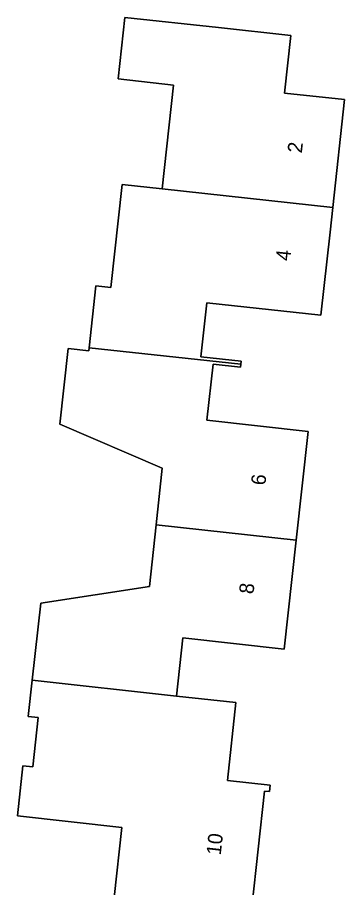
# Model space of a CAD drawing. Extents: x 162184 to 163154, y 385507 to 386516.
# Drawn here: x 162362.2 to 162384.7, y 385954.9 to 386014.8 of the extents above; entities that cross this region are included whole.
import ezdxf

# ---------------------------------------------------------------- set-up
doc = ezdxf.new("R2010")
doc.units = 0
for name, color, linetype in [('IMGEO_Erf', 7, 'Continuous'), ('IMGEO_Pand', 7, 'Continuous'), ('IMGEO_Pand_nummerreeks', 7, 'Continuous')]:
    doc.layers.add(name, color=color, linetype=linetype)

msp = doc.modelspace()

# ---------------------------------------------------------------- linework, layer by layer
at = {"layer": 'IMGEO_Erf'}
msp.add_lwpolyline([(162368.88, 385954.232), (162369.409, 385959.063), (162362.221, 385959.849), (162362.599, 385963.299), (162363.272, 385963.226), (162363.643, 385966.619), (162362.97, 385966.693), (162363.244, 385969.193), (162363.824, 385974.493), (162371.294, 385975.64), (162371.757, 385979.872), (162372.183, 385983.765), (162365.134, 385986.792), (162365.705, 385992.01), (162367.131, 385991.853), (162367.154, 385992.06), (162367.619, 385996.314), (162368.645, 385996.202), (162369.422, 386003.291), (162372.164, 386002.991), (162372.945, 386010.127), (162369.138, 386010.543), (162369.601, 386014.78), (162376.041, 386014.075), (162381.011, 386013.531), (162380.579, 386009.576), (162384.718, 386009.123), (162383.907, 386001.705), (162383.719, 386000), (162383.094, 385994.286), (162375.248, 385995.144), (162374.842, 385991.43), (162377.596, 385991.128), (162377.573, 385990.92), (162377.55, 385990.71), (162375.674, 385990.916), (162375.252, 385987.066), (162382.212, 385986.304), (162381.393, 385978.817), (162380.574, 385971.331), (162373.587, 385972.095), (162373.149, 385968.09), (162377.25, 385967.641), (162376.664, 385962.284), (162379.61, 385961.962), (162379.562, 385961.522), (162379.221, 385961.559), (162378.348, 385953.58)], dxfattribs=at)
at = {"layer": 'IMGEO_Pand'}
for points in [[(162383.907, 386001.705), (162384.718, 386009.123), (162380.579, 386009.576), (162381.011, 386013.531), (162376.041, 386014.075), (162369.601, 386014.78), (162369.138, 386010.543), (162372.945, 386010.127), (162372.164, 386002.991)], [(162367.154, 385992.06), (162377.573, 385990.92), (162377.596, 385991.128), (162374.842, 385991.43), (162375.248, 385995.144), (162383.094, 385994.286), (162383.719, 386000), (162383.907, 386001.705), (162372.164, 386002.991), (162369.422, 386003.291), (162368.645, 385996.202), (162367.619, 385996.314)], [(162371.757, 385979.872), (162381.393, 385978.817), (162382.212, 385986.304), (162375.252, 385987.066), (162375.674, 385990.916), (162377.55, 385990.71), (162377.573, 385990.92), (162367.154, 385992.06), (162367.131, 385991.853), (162365.705, 385992.01), (162365.134, 385986.792), (162372.183, 385983.765)], [(162363.244, 385969.193), (162373.149, 385968.09), (162373.587, 385972.095), (162380.574, 385971.331), (162381.393, 385978.817), (162371.757, 385979.872), (162371.294, 385975.64), (162363.824, 385974.493)], [(162368.88, 385954.232), (162373.668, 385953.708), (162378.638, 385953.164), (162378.68, 385953.544), (162378.348, 385953.58), (162379.221, 385961.559), (162379.562, 385961.522), (162379.61, 385961.962), (162376.664, 385962.284), (162377.25, 385967.641), (162373.149, 385968.09), (162363.244, 385969.193), (162362.97, 385966.693), (162363.643, 385966.619), (162363.272, 385963.226), (162362.599, 385963.299), (162362.221, 385959.849), (162369.409, 385959.063)]]:
    msp.add_lwpolyline(points, close=True, dxfattribs=at)

# ---------------------------------------------------------------- texts
at = {"layer": 'IMGEO_Pand_nummerreeks'}
for s, rotation, p in [('2', 83.76834, (162381.777, 386005.412)), ('4', 83.73865, (162380.966, 385997.997)), ('6', 83.75684, (162379.268, 385982.561)), ('8', 83.75684, (162378.449, 385975.079)), ('10', 83.75598, (162376.2, 385957.116))]:
    msp.add_text(s, height=1, rotation=rotation, dxfattribs=at).set_placement(p)

doc.saveas('drawing.dxf')
